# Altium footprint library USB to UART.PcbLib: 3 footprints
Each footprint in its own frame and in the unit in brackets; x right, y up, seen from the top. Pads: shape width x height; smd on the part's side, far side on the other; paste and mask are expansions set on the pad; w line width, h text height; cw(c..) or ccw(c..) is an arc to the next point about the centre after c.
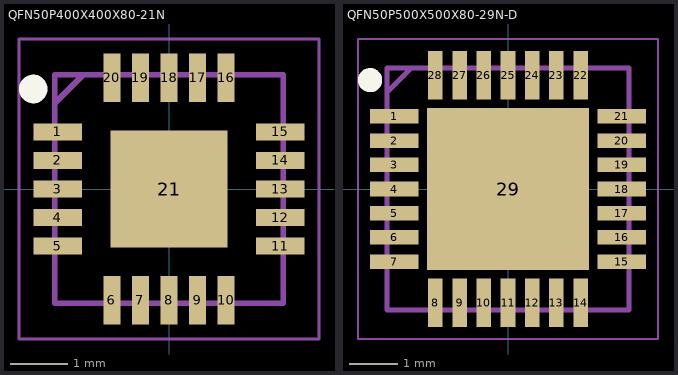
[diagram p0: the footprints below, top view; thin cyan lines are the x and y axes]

## PCBComponent_1 [mm]

## QFN50P400X400X80-21N [mm]
pads (21):
  rect 0.85x0.3 smd: 1(-1.95,1) 2(-1.95,0.5) 3(-1.95,0) 4(-1.95,-0.5) 5(-1.95,-1) 11(1.95,-1) 12(1.95,-0.5) 13(1.95,0) 14(1.95,0.5) 15(1.95,1)
  rect 0.3x0.85 smd: 6(-1,-1.95) 7(-0.5,-1.95) 8(0,-1.95) 9(0.5,-1.95) 10(1,-1.95) 16(1,1.95) 17(0.5,1.95) 18(0,1.95) 19(-0.5,1.95) 20(-1,1.95)
  rect 2.05x2.05 smd: 21(0,0)
Top Overlay:
  circle w0.25: c-2.375,1.75 r0.125
Mechanical 13:
  lines w0.1: -2,1.5 -1.5,2 ; -2,-2 -2,2 2,2 2,-2 -2,-2
Mechanical 15:
  lines w0.05: -2.625,-2.625 -2.625,2.625 2.625,2.625 2.625,-2.625 -2.625,-2.625
3D body "FT231XQ-R.stp": height 0.8, standoff 0, extent -2.05,-2.05 2.05,2.05

## QFN50P500X500X80-29N-D [mm]
pads (29):
  rect 1x0.3 smd: 1(-2.35,1.5) 2(-2.35,1) 3(-2.35,0.5) 4(-2.35,0) 5(-2.35,-0.5) 6(-2.35,-1) 7(-2.35,-1.5) 15(2.35,-1.5) 16(2.35,-1) 17(2.35,-0.5) 18(2.35,0) 19(2.35,0.5) 20(2.35,1) 21(2.35,1.5)
  rect 0.3x1 smd: 8(-1.5,-2.35) 9(-1,-2.35) 10(-0.5,-2.35) 11(0,-2.35) 12(0.5,-2.35) 13(1,-2.35) 14(1.5,-2.35) 22(1.5,2.35) 23(1,2.35) 24(0.5,2.35) 25(0,2.35) 26(-0.5,2.35) 27(-1,2.35) 28(-1.5,2.35)
  rect 3.35x3.35 smd: 29(0,0)
Top Overlay:
  circle w0.25: c-2.85,2.25 r0.125
Mechanical 13:
  lines w0.1: -2.5,2 -2,2.5 ; -2.5,-2.5 -2.5,2.5 2.5,2.5 2.5,-2.5 -2.5,-2.5
Mechanical 15:
  lines w0.05: -3.1,-3.1 -3.1,3.1 3.1,3.1 3.1,-3.1 -3.1,-3.1
3D body "CP2102N-A02-GQFN28.stp": height 0.8, standoff 0, extent -2.55,-2.55 2.55,2.55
